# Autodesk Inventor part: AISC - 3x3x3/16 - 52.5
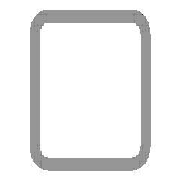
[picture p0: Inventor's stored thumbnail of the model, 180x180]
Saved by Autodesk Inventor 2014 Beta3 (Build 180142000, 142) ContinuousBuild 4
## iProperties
IsCustomPart: 1
_CCFamilyMember: 9
_CCFamilyDisplayName: ANSI AISC (Square) - Tube
_FrameMemberDoc: Frame Member File
_Version: 15.0.0
_GetPNFromCC: 1
Created: 2011-01
Part Number: AISC - 3x3x3/16 - 52.5
Material: Steel, Mild
Description: Tube
Document SubType Name: Modeling
Standard: ANSI
Designer: Beta-8540w
Standards Organization: ANSI
Language: en-US
Size Designation: 3x3x3/16
Categories: <MemberInstance><Categories><Category DisplayName="Structural Shapes" InternalName="089c4875-fa83-4c05-b084-43b9cc11f5ed" Mnemonic="GRDR"><CategoryParameter Dis
Stock Number: 3x3x3/16
Density: 7.86 g/cm^3
Appearance: Steel
G_W: 3.000 in
G_H: 3.000 in
G_L: 52.500 in
Author: Beta-8540w
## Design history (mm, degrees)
node "Start plane"
node "End plane"
sketch "Sketch"
  geometry: L1 (-38.1, -28.575)-(-38.1, 28.575); L2 (-28.575, 38.1)-(28.575, 38.1); L3 (38.1, 28.575)-(38.1, -28.575); L4 (28.575, -38.1)-(-28.575, -38.1); L5 (-28.575, 33.337)-(28.575, 33.338); L6 (33.338, 28.575)-(33.338, -28.575); L7 (28.575, -33.337)-(-28.575, -33.338); L8 (-33.338, -28.575)-(-33.338, 28.575); L9 (0, 56.102)-(0, -56.102) reference; L10 (-56.102, 0)-(56.102, 0) reference; A1 r 9.525 centre (-28.575, -28.575) between (-38.1, -28.575) and (-28.575, -38.1); A2 r 9.525 centre (-28.575, 28.575) between (-28.575, 38.1) and (-38.1, 28.575); A3 r 9.525 centre (28.575, 28.575) between (38.1, 28.575) and (28.575, 38.1); A4 r 9.525 centre (28.575, -28.575) between (28.575, -38.1) and (38.1, -28.575); A5 r 4.763 centre (-28.575, 28.575) between (-28.575, 33.337) and (-33.338, 28.575); A6 r 4.763 centre (28.575, 28.575) between (33.338, 28.575) and (28.575, 33.338); A7 r 4.763 centre (28.575, -28.575) between (28.575, -33.337) and (33.338, -28.575); A8 r 4.763 centre (-28.575, -28.575) between (-33.338, -28.575) and (-28.575, -33.338)
  constraints: 16 end point, 16 point on circle, 8 centre point, 8 tangent, 4 parallel, 3 equal radius, 2 perpendicular, 7 other
  dimensions: "d10" = 76.2 distance between parallel lines of L2 L4 (= G_H); "d11" = 76.2 distance between parallel lines of L1 L3 (= G_W); "d12" = 4.7625 distance between parallel lines of L3 L6 (= G_T); "d15" = 38.1 distance between parallel lines of L2 L10 (= 0.5 x d10); "d16" = 38.1 distance between parallel lines of L9 L3 (= 0.5 x d11); "d17" = 9.525 radius of A1 (= G_IR)
extrude "Body" new body sketch "Sketch" stored distance "d3" = 1333.5 (= G_L); taper "d4" = 0 deg
node "Driven Length"
  sketch "Sketch3"
    geometry: L1 (0, 0)-(10, 0) reference
    constraints: 2 end point, 1 horizontal
  workplane "Work Plane3"
  sketch "Sketch4"
    geometry: L1 (-2, 38.1)-(12, 38.1) reference; L2 (-2, 1371.6)-(12, 1371.6) reference
    dimensions: "d19" = 1333.5 distance between parallel lines of L1 L2 (derived)
workplane "Work Plane4"
split "Split1"
body "Solid1"
other parameters: "G_W" = 76.2 [user parameter; used in 1 equation term], "G_H" = 76.2 [user parameter; used in 1 equation term], "G_T" = 4.7625 [user parameter; used in 1 equation term], "G_IR" = 9.525 [user parameter; used in 1 equation term], "G_L" = 1333.5 (= d19) [user parameter; used in 1 equation term], "G_OFFSET_START" = -38.1 [user parameter; used in 1 equation term], "G_OFFSET_END" = 0 [user parameter; used in 1 equation term], "d13" = 38.1 (= -G_OFFSET_START), "d14" = 1371.6 (= G_OFFSET_END + B_L), "B_L" = 1371.6 [user parameter; used in 1 equation term], "d18" = 90 deg
